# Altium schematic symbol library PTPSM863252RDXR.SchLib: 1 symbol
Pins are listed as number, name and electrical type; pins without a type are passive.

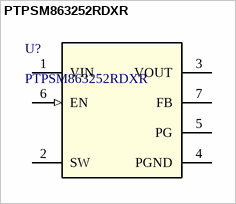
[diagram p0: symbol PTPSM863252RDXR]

## PTPSM863252RDXR
designator U?
3-V to 17-V input voltage, 3-A Eco-mode synchronous buck module 7-QFN-FCMOD -40 to 125; Manufacturer_Name: Texas Instruments
footprint RDX0007A-MFG
pins: 1 VIN (power), 2 SW, 3 VOUT (power), 4 PGND (power), 5 PG (oc), 6 EN (in), 7 FB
